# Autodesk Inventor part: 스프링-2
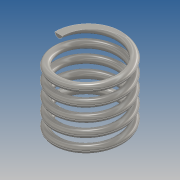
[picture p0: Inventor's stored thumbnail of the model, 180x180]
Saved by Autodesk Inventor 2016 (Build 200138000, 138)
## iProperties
Created: 2016-03
Part Number: 스프링-2
Material: 스테인레스 스틸
Document SubType Name: Modeling
Designer: Administrator
Density: 8 g/cm^3
Appearance: 반연마
Mass: 6.54721 g
Surface Area: 16.7036 cm^2
Volume: 0.818401 cm^3
Author: Administrator
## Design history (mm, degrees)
sketch "스케치1"
  geometry: L1 (0, 0)-(8.5, 0); L2 (8.5, 0)-(8.5, 17.5); L3 (8.5, 17.5)-(0, 17.5); L4 (0, 17.5)-(0, 0); C1 r 1 at (8.5, 0)
  constraints: 8 end point, 2 parallel, 1 centre point, 1 coincident, 1 horizontal, 1 perpendicular
  dimensions: "d0" = 17.5 distance of L1.end L2.end (derived); "d1" = 17 diameter of L2 L4; "d2" = 2 diameter of C1
feature "코일1" pitch "d3" = 10; turns "d5" = 5; dims "d4" = 17.5 (= d0), "d6" = 0, angle "d7" = 90 deg, angle "d8" = 90 deg, "d9" = 0, "d10" = 0
sketch "스케치2"
  geometry: L1 (4.1, 0)-(-21.424, 0); L2 (-21.424, 0)-(-21.424, -13.495); L3 (-21.424, -13.495)-(4.1, -13.495); L4 (4.1, -13.495)-(4.1, 0); 3 further points
  constraints: 8 end point, 2 parallel, 1 horizontal, 1 horizontal alignment, 1 perpendicular, 1 point on line
extrude "돌출1" cut sketch "스케치2" stored distance "d11" = 0; taper "d12" = 0 deg
sketch "스케치3"
  geometry: L1 (-2.819, 0)-(17.433, 0); L2 (17.433, 0)-(17.433, 5.421); L3 (17.433, 5.421)-(-2.819, 5.421); L4 (-2.819, 5.421)-(-2.819, 0); 3 further points
  constraints: 8 end point, 2 parallel, 1 horizontal, 1 horizontal alignment, 1 perpendicular, 1 point on line
extrude "돌출2" cut sketch "스케치3" stored distance "d13" = 0; taper "d14" = 0 deg
node "솔리드1"
